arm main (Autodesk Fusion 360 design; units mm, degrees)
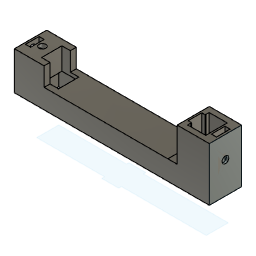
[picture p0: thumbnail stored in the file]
sketch "草图1" plane through (0, 0, 0) normal (0, 0, 1) x axis (1, 0, 0)
  line L1 (57.5, 9.5) -> (-57.5, 9.5)
  line L2 (57.5, -9.5) -> (57.5, 9.5)
  line L3 (-57.5, -9.5) -> (57.5, -9.5)
  line L4 (-57.5, 9.5) -> (-57.5, -9.5)
  line L5 (57.5, -9.5) -> (-57.5, 9.5)
  line L6 (-57.5, -9.5) -> (57.5, 9.5)
  point P6 (0, 0)
  point P1 (0, 0)
  point P4 (57.5, -9.5)
  point P5 (-57.5, -9.5)
  horizontal L1
  perpendicular L1 L2
  parallel L1 L3
  parallel L2 L4
  coincident L5 P6
  coincident L6 P6
  coincident P1 P6
  dimension "d1" distance P4 P5 = 115
  dimension "d2" distance L1 L3 = 19
extrude "拉伸1" new body sketch "草图1" profile of L1 L2 L3 L4 along normal blind 10
sketch "草图2" plane through (0, 0, 10) normal (0, 0, 1) x axis (-1, 0, 0)
  line L1 (-57.5, 9.5) -> (57.5, 9.5)
  line L2 (-57.5, -9.5) -> (-57.5, 9.5)
  line L3 (57.5, -9.5) -> (-57.5, -9.5)
  line L4 (57.5, 9.5) -> (57.5, -9.5)
  line L5 (-38.5, 9.5) -> (-57.5, 9.5)
  line L6 (-38.5, -9.5) -> (-38.5, 9.5)
  line L7 (-57.5, -9.5) -> (-38.5, -9.5)
  line L8 (-57.5, 9.5) -> (-57.5, -9.5)
  point P3 (-57.5, 9.5)
  point P6 (-57.5, 9.5)
  point P7 (-38.5, 9.5)
  horizontal L5
  vertical L6
  horizontal L7
  vertical L8
  coincident P3 P6
  dimension "d5" distance P6 P7 = 19
extrude "拉伸2" add sketch "草图2" profile of L1 L2 L3 L5 L6 L7 L8 along normal blind 20
sketch "草图3" plane through (0, 0, 30) normal (0, 0, 1) x axis (-1, 0, 0)
  line L1 (-38.5, -9.5) -> (-57.5, -9.5)
  line L2 (-38.5, 9.5) -> (-38.5, -9.5)
  line L3 (-57.5, 9.5) -> (-38.5, 9.5)
  line L4 (-57.5, -9.5) -> (-57.5, 9.5)
  line L5 (-41.5, 6.353) -> (-52.2, 6.353)
  line L6 (-52.2, -6.347) -> (-41.5, -6.347)
  line L7 (-41.5, -6.347) -> (-52.2, 6.353)
  line L8 (-52.2, -6.347) -> (-41.5, 6.353)
  line L9 (-52.2, -5.5) -> (-52.2, -6.347)
  line L10 (-52.2, 6.353) -> (-52.2, 5.5)
  line L11 (-52.2, -5.5) -> (-52.2, 5.5)
  line L12 (-41.5, 4.5005) -> (-41.5, 6.353)
  line L13 (-41.5, -6.347) -> (-41.5, -4.4995)
  line L14 (-39.5, 3.9901) -> (-41.5, 3.9901)
  line L15 (-39.5, -4.0099) -> (-39.5, 3.9901)
  line L16 (-41.5, -4.0099) -> (-39.5, -4.0099)
  line L17 (-39.5, -4.0099) -> (-41.5, 3.9901)
  line L18 (-41.5, -4.0099) -> (-39.5, 3.9901)
  line L19 (-56.2, 4) -> (-53.2, 4)
  line L20 (-56.2, -4) -> (-56.2, 4)
  line L21 (-53.2, -4) -> (-56.2, -4)
  line L22 (-53.2, 4) -> (-53.2, -4)
  line L23 (-56.2, -4) -> (-53.2, 4)
  line L24 (-53.2, -4) -> (-56.2, 4)
  line L25 (-41.5, 3.9901) -> (-41.5, 4.5005)
  line L26 (-41.5, -4.4995) -> (-41.5, -4.0099)
  point P10 (-46.85, 0.003)
  point P11 (-52.2, 5.5)
  point P20 (-40.5, -0.0099)
  point P15 (-40.5, -0.0099)
  point P25 (-54.7, 0)
  point P26 (-41.5, 3.9901)
  point P18 (-39.5, -4.0099)
  point P19 (-41.5, -4.0099)
  horizontal L5
  perpendicular L5 L12
  parallel L5 L6
  parallel L9 L12
  coincident L7 P10
  coincident L8 P10
  coincident P11 L9
  collinear L9 L10
  collinear L12 L13
  parallel L13 L25
  horizontal L14
  perpendicular L14 L15
  parallel L14 L16
  coincident L17 P20
  coincident L18 P20
  coincident P15 P20
  horizontal L19
  perpendicular L19 L20
  parallel L19 L21
  parallel L20 L22
  coincident L23 P25
  coincident L24 P25
  collinear L25 L26
  coincident L17 P26
  dimension "d24" distance L9 L12 = 10.7
  dimension "d25" distance L5 L6 = 12.7
  dimension "d26" distance L2 L12 = 3
  dimension "d32" distance P18 P19 = 2
  dimension "d33" distance L14 L16 = 8
  dimension "d34" distance P15 L25 = 1
  dimension "d35" distance L19 L21 = 8
  dimension "d36" distance L20 L22 = 3
  dimension "d37" distance L11 L22 = 1
sketch "草图4" plane through (38.5, 0, 0) normal (-1, 0, 0) x axis (0, -1, 0)
  line L1 (9.5, 10) -> (-9.5, 10)
  line L2 (9.5, 30) -> (9.5, 10)
  line L3 (-9.5, 30) -> (9.5, 30)
  line L4 (-9.5, 10) -> (-9.5, 30)
  circle C1 centre (0, 17) radius 2
  point P6 (0, 17)
  dimension "d20" diameter C1 = 4
  dimension "d21" distance L3 P6 = 13
extrude "拉伸6" cut sketch "草图3" profile of L5 L13 L6 L10 L11 L26 L14 L15 L16 against normal blind 47
extrude "拉伸7" cut sketch "草图3" profile of L19 L20 L21 L22 against normal blind 17
sketch "草图5" plane through (57.5, 0, 0) normal (1, 0, 0) x axis (0, 1, 0)
  line L1 (9.5, 0) -> (-9.5, 0)
  line L2 (9.5, 30) -> (9.5, 0)
  line L3 (-9.5, 30) -> (9.5, 30)
  line L4 (-9.5, 0) -> (-9.5, 30)
  circle C1 centre (0, 22) radius 2
  point P6 (0, 22)
  dimension "d42" diameter C1 = 4
  dimension "d43" distance L3 P6 = 8
extrude "拉伸8" cut sketch "草图5" profile of C1 against normal blind 13
sketch "草图6" plane through (0, 0, 10) normal (0, 0, 1) x axis (-1, 0, 0)
  line L1 (-38.5, -9.5) -> (-38.5, 9.5)
  line L2 (57.5, -9.5) -> (-38.5, -9.5)
  line L3 (57.5, 9.5) -> (57.5, -9.5)
  line L4 (-38.5, 9.5) -> (57.5, 9.5)
  line L5 (56.5, -4) -> (53.5, -4)
  line L6 (56.5, 4) -> (56.5, -4)
  line L7 (53.5, 4) -> (56.5, 4)
  line L8 (53.5, -4) -> (53.5, 4)
  line L9 (56.5, 4) -> (53.5, -4)
  line L10 (53.5, 4) -> (56.5, -4)
  circle C1 centre (50.5, 0) radius 2
  point P10 (55, 0)
  point P8 (56.5, 4)
  point P9 (53.5, 4)
  point P11 (50.5, 0)
  horizontal L5
  perpendicular L5 L6
  parallel L5 L7
  parallel L6 L8
  coincident L9 P10
  coincident L10 P10
  dimension "d48" distance P8 P9 = 3
  dimension "d49" distance L5 L7 = 8
  dimension "d131" diameter C1 = 4
  dimension "d132" distance L8 P11 = 3
extrude "拉伸10" cut sketch "草图6" profile of L5 L6 L7 L8 against normal blind 8
sketch "草图7" plane through (-57.5, 0, 0) normal (-1, 0, 0) x axis (0, -1, 0)
  line L1 (9.5, 0) -> (-9.5, 0)
  line L2 (9.5, 10) -> (9.5, 0)
  line L3 (-9.5, 10) -> (9.5, 10)
  line L4 (-9.5, 0) -> (-9.5, 10)
  circle C1 centre (0, 6) radius 2
  point P6 (0, 6)
  dimension "d56" diameter C1 = 4
  dimension "d57" distance L3 P6 = 4
sketch "草图9" plane through (0, 0, 0) normal (0, 0, -1) x axis (1, 0, 0)
  line L1 (-57.5, 9.5) -> (57.5, 9.5)
  line L2 (-57.5, -9.5) -> (-57.5, 9.5)
  line L3 (57.5, -9.5) -> (-57.5, -9.5)
  line L4 (57.5, 9.5) -> (57.5, -9.5)
  line L5 (-47.5, 6.3532) -> (52.5, 6.3532)
  line L6 (-47.5, -6.6468) -> (-47.5, 6.3532)
  line L7 (52.5, -6.6468) -> (-47.5, -6.6468)
  line L8 (52.5, 6.3532) -> (52.5, -6.6468)
  line L9 (41.5, -6.347) -> (52.2, -6.347)
  line L10 (41.5, -4.4995) -> (41.5, -6.347)
  line L11 (41.5, -4.0099) -> (41.5, -4.4995)
  line L12 (39.5, -4.0099) -> (41.5, -4.0099)
  line L13 (39.5, 3.9901) -> (39.5, -4.0099)
  line L14 (41.5, 3.9901) -> (39.5, 3.9901)
  line L15 (41.5, 4.5005) -> (41.5, 3.9901)
  line L16 (41.5, 6.353) -> (41.5, 4.5005)
  line L17 (52.2, 6.353) -> (41.5, 6.353)
  line L18 (52.2, -6.347) -> (52.2, 6.353)
  horizontal L5
  vertical L6
  horizontal L7
  vertical L8
  dimension "d70" distance L6 L8 = 100
  dimension "d71" distance L5 L7 = 13
extrude "拉伸12" cut sketch "草图9" profile of L5 L6 L7 against normal blind 3
sketch "草图10" plane through (0, 0, 3) normal (0, 0, -1) x axis (1, 0, 0)
  line L1 (41.5, -6.347) -> (52.2, -6.347)
  line L2 (52.2, 6.353) -> (41.5, 6.353)
  line L3 (-47.5, -6.6468) -> (-47.5, 6.3532)
  line L4 (56.2, -6.347) -> (52.2, -6.347)
  line L5 (56.2, 6.353) -> (56.2, -6.347)
  line L6 (52.2, 6.353) -> (56.2, 6.353)
  line L7 (52.2, -6.347) -> (52.2, 6.353)
  line L8 (52.5, 6.3532) -> (52.5, -6.6468)
  line L9 (41.5, 3.9901) -> (39.5, 3.9901)
  line L10 (41.5, 4.5005) -> (41.5, 3.9901)
  line L11 (41.5, 6.353) -> (41.5, 4.5005)
  line L12 (52.2, -6.347) -> (52.2, 6.353)
  line L13 (41.5, -4.4995) -> (41.5, -6.347)
  line L14 (41.5, -4.0099) -> (41.5, -4.4995)
  line L15 (39.5, -4.0099) -> (41.5, -4.0099)
  line L16 (39.5, 3.9901) -> (39.5, -4.0099)
  line L17 (-47.5, 6.3532) -> (52.5, 6.3532)
  line L18 (52.5, -6.6468) -> (-47.5, -6.6468)
  point P8 (56.2, 6.353)
  point P2 (52.2, -6.347)
  point P6 (52.2, -6.347)
  horizontal L4
  vertical L5
  horizontal L6
  vertical L7
  coincident L2 P8
  coincident P2 P6
  dimension "d65" distance L5 L7 = 4
extrude "拉伸14" cut sketch "草图10" profile of L1 L2 L3 L4 L5 L6 L7 against normal blind 19
sketch "草图12" plane through (0, 0, 0) normal (0, 0, -1) x axis (1, 0, 0)
  line L1 (-57.5, 9.5) -> (57.5, 9.5)
  line L2 (-57.5, -9.5) -> (-57.5, 9.5)
  line L3 (57.5, -9.5) -> (-57.5, -9.5)
  line L4 (57.5, 9.5) -> (57.5, -9.5)
  line L5 (-47.5, -6.6468) -> (52.5, -6.6468)
  line L6 (-47.5, 6.3532) -> (-47.5, -6.6468)
  line L7 (52.5, 6.3532) -> (-47.5, 6.3532)
  line L8 (2.5, -8) -> (-7.5, -8)
  line L9 (2.5, 8) -> (2.5, -8)
  line L10 (-7.5, 8) -> (2.5, 8)
  line L11 (-7.5, -8) -> (-7.5, 8)
  line L12 (52.5, -6.6468) -> (52.5, 6.3532)
  horizontal L8
  vertical L9
  horizontal L10
  vertical L11
  dimension "d68" distance L9 L11 = 10
  dimension "d69" distance L8 L10 = 16
  dimension "d72" distance L6 L11 = 40
extrude "拉伸17" add of existing geometry blind 1.5
sketch "草图14" plane through (0, 0, -1.5) normal (0, 0, -1) x axis (1, 0, 0)
  line L1 (-57.5, 9.5) -> (57.5, 9.5)
  line L2 (-57.5, -9.5) -> (-57.5, 9.5)
  line L3 (57.5, -9.5) -> (-57.5, -9.5)
  line L4 (57.5, 9.5) -> (57.5, -9.5)
  line L5 (-47.5, -6.6468) -> (52.5, -6.6468)
  line L6 (-47.5, 6.3532) -> (-47.5, -6.6468)
  line L7 (52.5, 6.3532) -> (-47.5, 6.3532)
  line L8 (52.5, -6.6468) -> (52.5, 6.3532)
  circle C1 centre (-51.5, 0) radius 1.5
extrude "拉伸18" add sketch "草图14" profile of C1 against normal blind 1
sketch "草图15" plane through (0, 0, -1.5) normal (0, 0, -1) x axis (1, 0, 0)
  line L1 (-57.5, 9.5) -> (57.5, 9.5)
  line L2 (-57.5, -9.5) -> (-57.5, 9.5)
  line L3 (57.5, -9.5) -> (-57.5, -9.5)
  line L4 (57.5, 9.5) -> (57.5, -9.5)
  line L5 (-47.5, -6.6468) -> (52.5, -6.6468)
  line L6 (-47.5, 6.3532) -> (-47.5, -6.6468)
  line L7 (52.5, 6.3532) -> (-47.5, 6.3532)
  line L8 (2.5, -8) -> (-7.5, -8)
  line L9 (2.5, -6.6468) -> (2.5, -8)
  line L10 (-7.5, -6.6468) -> (2.5, -6.6468)
  line L11 (-7.5, -8) -> (-7.5, -6.6468)
  line L12 (-7.5, 6.3532) -> (2.5, 6.3532)
  line L13 (-7.5, 8) -> (-7.5, 6.3532)
  line L14 (2.5, 8) -> (-7.5, 8)
  line L15 (2.5, 6.3532) -> (2.5, 8)
  line L16 (52.5, -6.6468) -> (52.5, 6.3532)
  point P12 (2.5, -6.6468)
  point P14 (2.5, 6.3532)
  horizontal L8
  vertical L9
  horizontal L10
  vertical L11
  midpoint L5 P12
  horizontal L12
  vertical L13
  horizontal L14
  vertical L15
  midpoint L7 P14
extrude "拉伸19" cut sketch "草图15" profile of L5 L7 L8 L9 L10 L11 L12 L13 L14 L15 against normal blind 1
sketch "草图16" plane through (0, 0, -21) normal (0, 0, -1) x axis (1, 0, 0)
  line L1 (-7.5, 8) -> (2.5, 8)
  line L2 (-7.5, 6.3532) -> (-7.5, 8)
  line L3 (-47.5, 6.3532) -> (-7.5, 6.3532)
  line L4 (-47.5, -6.6468) -> (-47.5, 6.3532)
  line L5 (-7.5, -6.6468) -> (-47.5, -6.6468)
  line L6 (-7.5, -8) -> (-7.5, -6.6468)
  line L7 (2.5, -8) -> (-7.5, -8)
  line L8 (2.5, -6.6468) -> (2.5, -8)
  line L9 (52.5, -6.6468) -> (2.5, -6.6468)
  line L10 (52.5, 6.3532) -> (52.5, -6.6468)
  line L11 (2.5, 6.3532) -> (52.5, 6.3532)
  line L12 (2.5, 8) -> (2.5, 6.3532)
sketch "草图17" plane through (0, 0, 10) normal (0, 0, 1) x axis (-1, 0, 0)
  line L1 (53.5, -4) -> (56.5, -4)
  line L2 (53.5, 4) -> (53.5, -4)
  line L3 (56.5, 4) -> (53.5, 4)
  line L4 (56.5, -4) -> (56.5, 4)
  line L5 (-38.5, -9.5) -> (-38.5, 9.5)
  line L6 (57.5, -9.5) -> (-38.5, -9.5)
  line L7 (57.5, 9.5) -> (57.5, -9.5)
  line L8 (-38.5, 9.5) -> (57.5, 9.5)
extrude "拉伸20" add sketch "草图17" along normal blind 11
sketch "草图19" plane through (0, 9.5, 0) normal (0, 1, 0) x axis (-1, 0, 0)
  line L1 (57.5, 10) -> (-38.5, 10)
  line L2 (57.5, 21) -> (57.5, 10)
  line L3 (-38.5, 21) -> (57.5, 21)
  line L4 (-33, 21) -> (40, 21)
  line L5 (40, 10) -> (-33, 10)
  line L6 (40, 21) -> (40, 10)
  line L7 (-33, 21) -> (-33, 10)
  line L8 (-38.5, 10) -> (-38.5, 21)
  point P6 (40, 21)
  horizontal L4
  horizontal L5
  vertical L6
  coincident L3 P6
extrude "拉伸22" cut sketch "草图19" profile of L1 L3 L4 L5 L6 L7 against normal blind 30
sketch "草图20" plane through (-57.5, 0, 0) normal (-1, 0, 0) x axis (0, -1, 0)
  line L1 (9.5, 21) -> (9.5, -1.5)
  line L2 (-9.5, 21) -> (9.5, 21)
  line L3 (-9.5, 10) -> (-9.5, 21)
  line L4 (-9.5, -1.5) -> (-9.5, 10)
  line L5 (9.5, -1.5) -> (-9.5, -1.5)
  circle C1 centre (0, 17) radius 2
  point P7 (0, 17)
  dimension "d119" diameter C1 = 4
  dimension "d120" distance L2 P7 = 4
extrude "拉伸23" cut sketch "草图20" profile of C1 against normal blind 6
extrude "拉伸25" cut sketch "草图6" profile of C1 along normal blind 16
sketch "草图22" plane through (0, -9.5, 0) normal (0, -1, 0) x axis (1, 0, 0)
  line L1 (33, 10) -> (33, 21)
  line L2 (-40, 10) -> (33, 10)
  line L3 (-40, 21) -> (-40, 10)
  line L4 (-57.5, 21) -> (-40, 21)
  line L5 (-57.5, -1.5) -> (-57.5, 21)
  line L6 (57.5, -1.5) -> (-57.5, -1.5)
  line L7 (57.5, 30) -> (57.5, -1.5)
  line L8 (38.5, 30) -> (57.5, 30)
  line L9 (38.5, 21) -> (38.5, 30)
  line L10 (33, 21) -> (38.5, 21)
  line L11 (38.5, 10) -> (33, 10)
  line L12 (38.5, 21) -> (38.5, 10)
  line L13 (33, 21) -> (38.5, 21)
  line L14 (33, 10) -> (33, 21)
  point P11 (38.5, 21)
  point P14 (38.5, 21)
  point P3 (33, 10)
  point P12 (33, 10)
  horizontal L11
  vertical L12
  horizontal L13
  vertical L14
  coincident P11 P14
  coincident P3 P12
extrude "拉伸26" cut sketch "草图22" profile of L1 L10 L11 L12 L13 L14 against normal blind 70
sketch "草图23" plane through (0, 0, 30) normal (0, 0, 1) x axis (-1, 0, 0)
  line L1 (-53.2, 4) -> (-56.2, 4)
  line L2 (-53.2, -4) -> (-53.2, 4)
  line L3 (-56.2, -4) -> (-53.2, -4)
  line L4 (-56.2, 4) -> (-56.2, -4)
  line L5 (-52.2, -6.347) -> (-41.5, -6.347)
  line L6 (-52.2, 6.353) -> (-52.2, -6.347)
  line L7 (-41.5, 6.353) -> (-52.2, 6.353)
  line L8 (-41.5, 4.5005) -> (-41.5, 6.353)
  line L9 (-41.5, 3.9901) -> (-41.5, 4.5005)
  line L10 (-39.5, 3.9901) -> (-41.5, 3.9901)
  line L11 (-39.5, -4.0099) -> (-39.5, 3.9901)
  line L12 (-41.5, -4.0099) -> (-39.5, -4.0099)
  line L13 (-41.5, -4.4995) -> (-41.5, -4.0099)
  line L14 (-41.5, -6.347) -> (-41.5, -4.4995)
  line L15 (-38.5, -9.5) -> (-57.5, -9.5)
  line L16 (-38.5, 9.5) -> (-38.5, -9.5)
  line L17 (-57.5, 9.5) -> (-38.5, 9.5)
  line L18 (-57.5, -9.5) -> (-57.5, 9.5)
extrude "拉伸27" add sketch "草图23" against normal blind 27
sketch "草图24" plane through (57.5, 0, 0) normal (1, 0, 0) x axis (0, 1, 0)
  line L1 (-9.5, -1.5) -> (-9.5, 30)
  line L2 (9.5, -1.5) -> (-9.5, -1.5)
  line L3 (9.5, 30) -> (9.5, -1.5)
  line L4 (-9.5, 30) -> (9.5, 30)
sketch "草图25" plane through (57.5, 0, 0) normal (1, 0, 0) x axis (0, 1, 0)
  line L1 (-9.5, 30) -> (9.5, 30)
  circle C1 centre (0, 17) radius 2
  point P2 (0, 17)
  dimension "d139" diameter C1 = 4
  dimension "d140" distance P2 L1 = 13
extrude "拉伸28" cut sketch "草图25" profile of C1 against normal blind 11
extrude "拉伸29" cut of existing geometry blind -5
sketch "草图26" plane through (0, 0, 10) normal (0, 0, 1) x axis (-1, 0, 0)
  line L1 (-33, 9.5) -> (40, 9.5)
  line L2 (-33, -9.5) -> (-33, 9.5)
  line L3 (40, -9.5) -> (-33, -9.5)
  line L4 (40, 9.5) -> (40, -9.5)
  line L5 (45, -6) -> (35, -6)
  line L6 (45, 6) -> (45, -6)
  line L7 (35, 6) -> (45, 6)
  line L8 (35, -6) -> (35, 6)
  line L9 (45, 6) -> (35, -6)
  line L10 (35, 6) -> (45, -6)
  point P10 (40, 0)
  horizontal L5
  perpendicular L5 L6
  parallel L5 L7
  parallel L6 L8
  coincident L9 P10
  coincident L10 P10
  midpoint L4 P10
extrude "拉伸30" cut sketch "草图26" profile of L4 L5 L7 L8 against normal blind 27
sketch "草图27" plane through (0, 0, 8) normal (0, 0, -1) x axis (1, 0, 0)
  line L1 (-40, -6) -> (-35, -6)
  line L2 (-40, 6) -> (-40, -6)
  line L3 (-35, 6) -> (-40, 6)
  line L4 (-35, -6) -> (-35, 6)
  line L5 (52.5, 6.3532) -> (52.5, -6.6468)
  line L6 (-47.5, 6.3532) -> (52.5, 6.3532)
  line L7 (-47.5, -6.6468) -> (-47.5, 6.3532)
  line L8 (52.5, -6.6468) -> (-47.5, -6.6468)
  line L9 (52.2, -6.347) -> (52.2, 6.353)
  line L10 (41.5, -6.347) -> (52.2, -6.347)
  line L11 (41.5, -4.4995) -> (41.5, -6.347)
  line L12 (41.5, -4.0099) -> (41.5, -4.4995)
  line L13 (39.5, -4.0099) -> (41.5, -4.0099)
  line L14 (39.5, 3.9901) -> (39.5, -4.0099)
  line L15 (41.5, 3.9901) -> (39.5, 3.9901)
  line L16 (41.5, 4.5005) -> (41.5, 3.9901)
  line L17 (41.5, 6.353) -> (41.5, 4.5005)
  line L18 (52.2, 6.353) -> (41.5, 6.353)
  line L19 (-45, 6) -> (-40, 6)
  line L20 (-45, -6) -> (-45, 6)
  line L21 (-40, -6) -> (-45, -6)
  line L22 (-40, -6) -> (-40, 6)
  point P4 (-40, 6)
  point P22 (-40, 6)
  point P3 (-40, -6)
  point P23 (-40, -6)
  horizontal L19
  vertical L20
  horizontal L21
  coincident P4 P22
  coincident P3 P23
extrude "拉伸31" cut sketch "草图27" profile of L2 L19 L20 L21 L22 against normal blind 34
extrude "拉伸32" cut of existing geometry blind -1
extrude "拉伸33" cut of existing geometry blind -1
